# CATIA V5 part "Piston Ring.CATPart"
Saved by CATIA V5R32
Part number: Piston Ring
Bounding box of the stored display mesh (mm): x -46.5 to 46.5, y -46.442 to 46.335, z 0 to 3
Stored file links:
  D:\PROJECTS\Project 2022\CATIA V5 6R 2022\Resources\Part Files\c13_catia_v5_6r2022_prt\c13_catia_v5-6r2022_figr_13-41\Part & Asm files\Piston Ring.CATPart
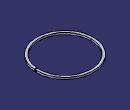
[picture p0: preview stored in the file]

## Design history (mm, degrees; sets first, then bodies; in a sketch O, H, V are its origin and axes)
Body1 (main body)
  Sketch1 on xy-plane, origin (0, 0, 0), H (1, 0, 0), V (0, 1, 0)
    circle A1 centre (0, 0) radius 46.5
    circle A2 centre (0, 0) radius 42.5
    radius A1 = 46.5
    radius A2 = 42.5
  Pad1: profile Sketch1, direction (0, 0, 1), length 3
  Sketch2 on yz-plane, origin (0, 0, 0), H (0, 1, 0), V (0, 0, 1)
    line L1 (2.5564, -3.2635) -> (-5.6312, 4.9241)
    line L2 (-5.6312, 4.9241) -> (-4.9241, 5.6312)
    line L3 (-4.9241, 5.6312) -> (3.2635, -2.5564)
    line L4 (3.2635, -2.5564) -> (2.5564, -3.2635)
    length L2 = 1
    distance O L1 = 0.5
    angle H L3 = 135
    parallelism: L4 L2, L1 L3
    perpendicularity: L1 L2
  Pocket1: profile Sketch2, direction (1, 0, 0), through (limit type 6)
